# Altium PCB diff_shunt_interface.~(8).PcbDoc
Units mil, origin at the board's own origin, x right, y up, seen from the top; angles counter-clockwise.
Board outline 420 x 600 mil, 2 copper layers (Top Layer, Bottom Layer), stack 16.1 mil thick; 5 components, 6 nets, 12 pads, 108 vias.
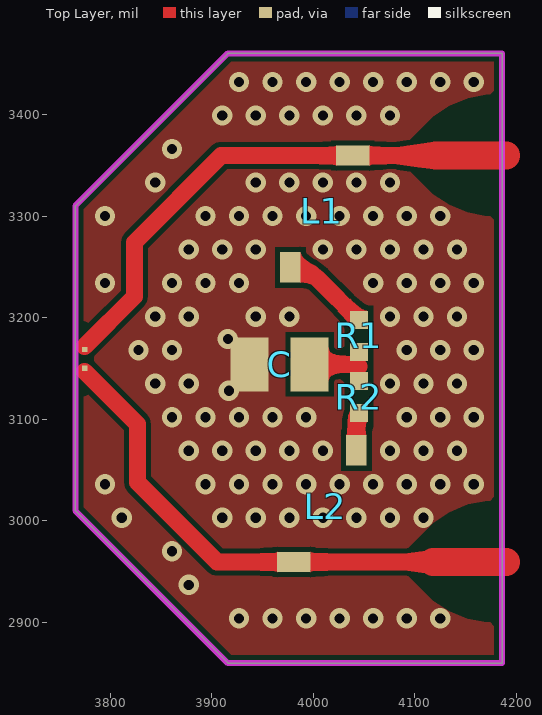
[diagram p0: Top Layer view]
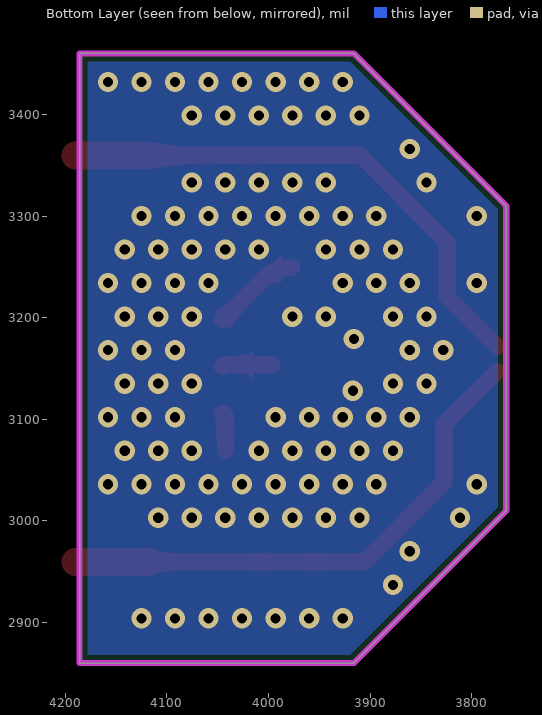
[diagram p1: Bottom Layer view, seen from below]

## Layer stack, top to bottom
Top Solder: solder mask 0.4, Solder Resist, Dk 3.5
Top Layer: signal copper 1.4
Dielectric 1: dielectric 13.3, FR-4, Dk 3.66
Bottom Layer: signal copper 1.4
Bottom Solder: solder mask 0.4, Solder Resist, Dk 3.5

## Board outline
3766,3010 3916,2860 4186,2860 4186,3460 3916,3460 3766,3310

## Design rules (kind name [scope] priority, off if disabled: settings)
Clearance Clearance_3 [InNet('NetL2_2') vs OnLayer('Keep-Out Layer')] p1: gap=-100 ignorepadtopadclearanceinfootprint=FALSE except(0: Arc-Hole Track-Hole SMDPad-Hole THPad-Hole Via-Hole Fill-Hole Poly-Hole Region-Hole Text-Hole)
Clearance Clearance_2 [InNet('NetL1_2') vs OnLayer('Keep-Out Layer')] p2: gap=-100 ignorepadtopadclearanceinfootprint=FALSE except(0: Arc-Hole Track-Hole SMDPad-Hole THPad-Hole Via-Hole Fill-Hole Poly-Hole Region-Hole Text-Hole)
Clearance Clearance_1 [InNet('No Net') vs InNet('GND')] p3: gap=50 ignorepadtopadclearanceinfootprint=FALSE except(0: Arc-Hole Track-Hole SMDPad-Hole THPad-Hole Via-Hole Fill-Hole Poly-Hole Region-Hole Text-Hole)
Clearance [All] p4: gap=5 ignorepadtopadclearanceinfootprint=FALSE except(0: Arc-Hole Track-Hole SMDPad-Hole THPad-Hole Via-Hole Fill-Hole Poly-Hole Region-Hole Text-Hole)
PolygonConnect [All] p1: connectstyle=Direct reliefconductorwidth=10 reliefentries=4 polygonreliefangle="90 Angle" airgapwidth=10
RoutingVias [All] p1: holewidth=28 width=50 viastyle="Through Hole" minholewidth=28 minwidth=50 maxholewidth=28 maxwidth=50
SolderMaskExpansion [All] p1: expansion=4 istentingtop=FALSE
Width [All] p1: maxlimit=50 minlimit=8 preferedwidth=16.82 impedanceprofiledriven=TRUE impedanceprofileid={C9EE0A32-63B8-435B-8C3B-82C28B80C81C} impedanceprofilevalue=50.000000 minimp=50.000000 maximp=50.000000 favimp=50.000000
30 further rules are at their usual default settings.

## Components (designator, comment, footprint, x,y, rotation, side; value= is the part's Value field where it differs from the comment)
C "CBR08C470FAGAC" FP-CBR08C-MFG 3967,3154 r0 top value="47 pF"
L1 "506WLSM0R70KT619T" 506WLS 4005,3307 r180 top
L2 "506WLSM0R70KT619T" 506WLS 4015,3012 r0 top
R1 "50R 0402" RESC1005X35X20LL05T10 4045,3182 r90 top
R2 "50R 0402" RESC1005X35X20LL05T10 4045,3122 r90 top

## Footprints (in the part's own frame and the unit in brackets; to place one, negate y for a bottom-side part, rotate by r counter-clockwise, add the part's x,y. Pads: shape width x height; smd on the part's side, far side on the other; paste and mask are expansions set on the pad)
506WLS [mil] "ATC conical inductor"
  rect 20x30 smd mask+1.97: 1(27.5,57.5)
  rect 33x20 smd mask+1.97: 2(-34,-52.5)
  body extent -45,-58 35,69, height 105
FP-CBR08C-MFG [mm]
  rect 0.95x1.35 smd paste+0 mask+0: 1(-0.75,0) 2(0.75,0)
  body extent -1.4,-0.85 1.4,0.85, height 0.25
RESC1005X35X20LL05T10 [mm] "Chip Resistor, 2-Leads, Body 1.00x0.50mm, IPC High Density"
  rect 0.45x0.45 smd: 1(-0.4,0) 2(0.4,0)
  body extent -0.53,-0.27 0.53,0.28, height 0.35

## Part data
C: library part CMP-03020-025427-1, "CAP CER 47PF 250V C0G/NP0 0805", Capacitance="47 pF", Manufacturer=KEMET, Package=CBR08C, Temperature="-55°C to +125°C", Temperature Characteristic=C0G, Temperature Coefficient=30ppm/°C, Temperature Range High=+125°C, Temperature Range Low=-55°C, Tolerance=0.01, Voltage Rating="250 V"
L1 L2: "coilcraft 700nH"
R1 R2: library part CMP-2002-03144-1, Manufacturer="TE Connectivity / AMP", Part Number=CPF0402B15K8E1

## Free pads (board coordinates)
  rect 5.12x5.12 smd: 2(3775.06,3150.16) 3(3775.06,3168.66)

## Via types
v1: diameter 20, hole 10, Top Layer to Bottom Layer, 108 vias

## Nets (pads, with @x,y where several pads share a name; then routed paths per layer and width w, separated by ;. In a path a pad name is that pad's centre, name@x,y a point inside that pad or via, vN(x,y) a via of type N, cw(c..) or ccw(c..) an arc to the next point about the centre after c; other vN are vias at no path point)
GND: C.1
  other v1: 3927,2904 3960,2904 3993,2904 4026,2904 4059,2904 4092,2904 4125,2904 3877.5,2937 3861,2970 3811.5,3003 3910.5,3003 3943.5,3003 3976.5,3003 4009.5,3003 4042.5,3003 4075.5,3003 4108.5,3003 3795,3036 3894,3036 3927,3036 3960,3036 3993,3036 4026,3036 4059,3036 4092,3036 4125,3036 4158,3036 3877.5,3069 3910.5,3069 3943.5,3069 3976.5,3069 4009.5,3069 4075.5,3069 4108.5,3069 4141.5,3069 3861,3102 3894,3102 3927,3102 3960,3102 3993,3102 4092,3102 4125,3102 4158,3102 3917,3128 3844.5,3135 3877.5,3135 4075.5,3135 4108.5,3135 4141.5,3135 3828,3168 3861,3168 4092,3168 4125,3168 4158,3168 3916,3179 3844.5,3201 3877.5,3201 3943.5,3201 3976.5,3201 4075.5,3201 4108.5,3201 4141.5,3201 3795,3234 3861,3234 3894,3234 3927,3234 4059,3234 4092,3234 4125,3234 4158,3234 3877.5,3267 3910.5,3267 3943.5,3267 4009.5,3267 4042.5,3267 4075.5,3267 4108.5,3267 4141.5,3267 3795,3300 3894,3300 3927,3300 3960,3300 3993,3300 4026,3300 4059,3300 4092,3300 4125,3300 3844.5,3333 3943.5,3333 3976.5,3333 4009.5,3333 4042.5,3333 4075.5,3333 3861,3366 3910.5,3399 3943.5,3399 3976.5,3399 4009.5,3399 4042.5,3399 4075.5,3399 3927,3432 3960,3432 3993,3432 4026,3432 4059,3432 4092,3432 4125,3432 4158,3432
NetC_2: C.2 R1.1 R2.2 | length 49
  Top Layer w16.82: C.2 4040.17,3154 cw(c4040.17,3147.17) 4045,3152
NetL1_1: L1.1 R1.2 | length 87.3
  Top Layer w16.82: L1.1 cw(c3977.5,3211.48) 4004.38,3238.36 R1.2
NetL1_2: L1.2 pad.3 | length 523.9
  Top Layer w16.82: 3775.06,3171.81 3824.07,3220.83 3824.07,3274.07 3909.5,3359.5 L1.2 4120.5,3359.5
  Top Layer w27.3: 4120.5,3359.5 4190,3359.5
NetL2_1: L2.1 R2.1 | length 37.4
  Top Layer w16.82: L2.1 4042.5,3100.22 cw(c4051.04,3100.22) R2.1
NetL2_2: L2.2 pad.2 | length 526
  Top Layer w16.82: 3775.06,3147.01 3827.02,3095.04 3827.02,3037.98 3905.5,2959.5 L2.2 4118,2959.5
  Top Layer w27.3: 4118,2959.5 4190,2959.5

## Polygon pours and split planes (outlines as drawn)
GND on Bottom Layer "Bottom Layer-No Net" (solid, pour order 0): 3766,3310 3916,3460 4186,3460 4186,2860 3916,2860 3766,3010
no net on Top Solder "NONET_L01_P002" (solid, pour order 2): 3766,3010 3916,2860 4186,2860 4186,3460 3916,3460 3766,3310
no net on Bottom Solder (solid, pour order 3): 3766,3010 3916,2860 4186,2860 4186,3460 3916,3460 3766,3310
GND on Top Layer "GND_L01_P001" (solid, pour order 1): 3765,3010 3915,2860 4185,2860 4185,3460 3915,3460 3765,3310

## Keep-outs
Keep-Out Layer:
  the board outline again, w6

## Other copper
Top Layer:
  pour cut-out: 4079.5,3359.5 4110.71,3390.71 cw(c4181.42,3320) 4181.42,3420 4190,3420 4190,3300 4180.42,3300 cw(c4179.71,3398.29) 4110.71,3328.29
  pour cut-out: 4079.5,2959.5 4110.71,2990.71 cw(c4181.42,2920) 4181.42,3020 4190,3020 4190,2900 4180.42,2900 cw(c4179.71,2998.29) 4110.71,2928.29

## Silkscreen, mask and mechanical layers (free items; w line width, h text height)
Top Solder:
  lines w27.3: 4120,2960 4185,2960 ; 4120.5,3360 4185.5,3360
